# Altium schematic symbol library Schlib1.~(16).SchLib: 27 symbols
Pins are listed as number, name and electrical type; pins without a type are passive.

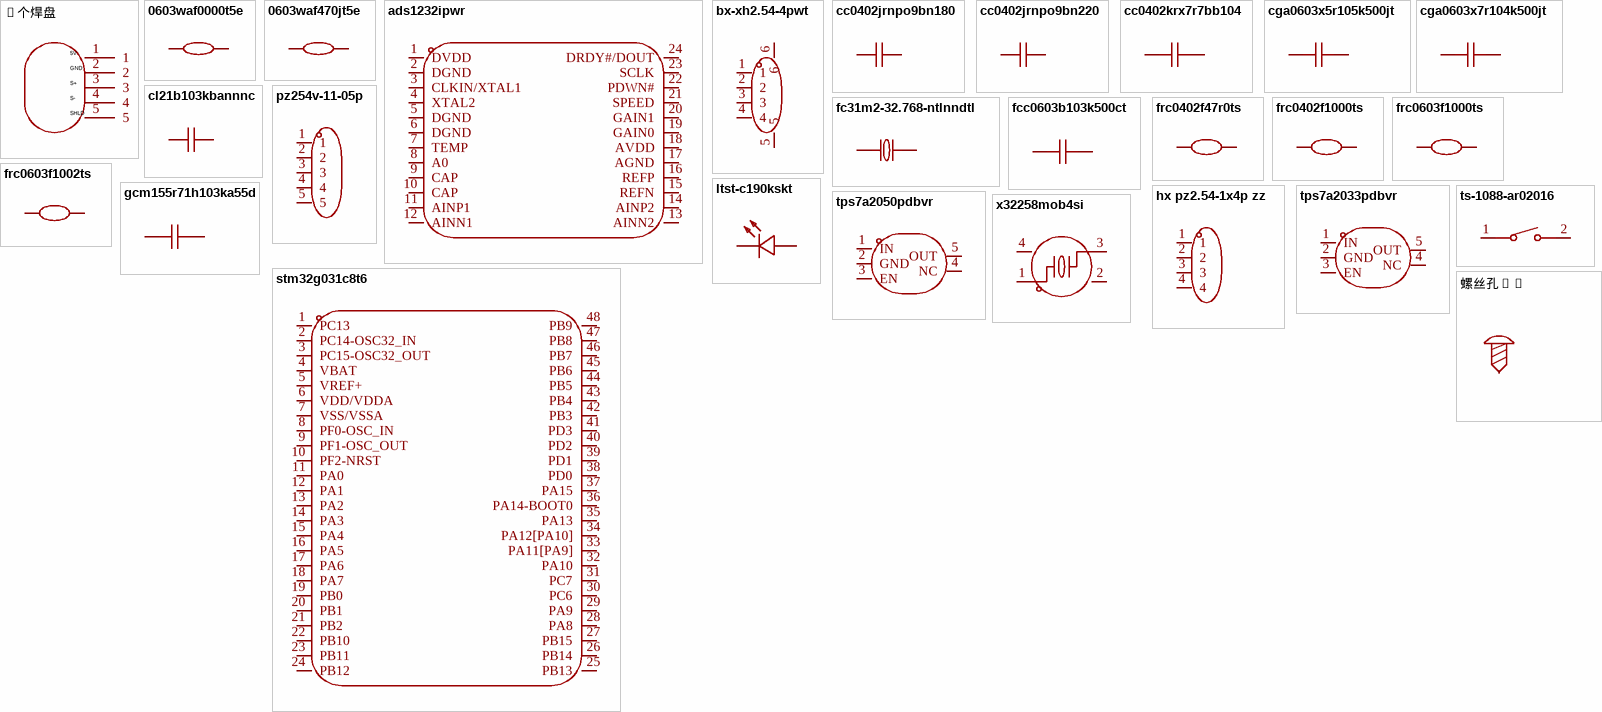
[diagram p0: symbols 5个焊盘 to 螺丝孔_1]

## 5个焊盘
designator U??  (value not drawn)
Convert to PCB: yes
pins: 1, 2, 3, 4, 5

## 0603waf0000t5e
designator R??  (value not drawn)
电阻类型:厚膜电阻;阻值:0Ω;精度:±1%;功率:100mW;工作电压:75V;温度系数:-;; Manufacturer: UNI-ROYAL(厚声); AddInBom: yes; ModelId: fc143cca1e79419f9cd78b61e9279f08; ModelName: R0603; ModelTransform: 31.8897,63.7794,0,90,0,0,0,0,0; Value: 0Ω; Tolerance: ±1%; Power(Watts): 100mW; Voltage-Supply(Max): 75V
footprint R0603
pins: 1, 2

## 0603waf470jt5e
designator R??  (value not drawn)
电阻类型:厚膜电阻;阻值:47Ω;精度:±1%;功率:100mW;工作电压:75V;温度系数:±100ppm/℃;; Manufacturer: UNI-ROYAL(厚声); AddInBom: yes; ModelId: fc143cca1e79419f9cd78b61e9279f08; ModelName: R0603; ModelTransform: 31.8897,63.7794,0,90,0,0,0,0,0; Value: 47Ω; Tolerance: ±1%; Power(Watts): 100mW; Voltage-Supply(Max): 75V
footprint R0603
pins: 1, 2

## ads1232ipwr
designator U??  (value not drawn)
分辨率(位):24;采样率:10Hz;工作电压:2.7V~5.3V;接口类型:SPI;; Manufacturer: TI(德州仪器); AddInBom: yes; ModelId: 57e278220af748a2882c4abba4094eb9; ModelName: TSSOP-24_L7.8-W4.4-H1.0-LS6.4-P0.65; ModelTransform: 252.188,307.086,0,90,0,0,0,0,0; Resolution (Bits): 24; Sampling Rate: 10Hz; number of channels: 2; Interface: SPI; differential input: 是; Clock/Oscillator: 内置；外置; Clock Frequency: 4.9152MHz；200kHz~8MHz; Voltage Reference: 外置; Programmable Gain: 支持; Temperature Sensors: 内置; ADC architecture: Sigma-Delta; Data rate: 80Hz；10Hz; Quiescent Current (Iq): 1.3uA; Full-Scale Range(FSR): 39mV；1.25V；19.5mV；2.5V
footprint TSSOP-24_L7.8-W4.4-P0.65-LS6.4-BL
footprint Model Name (Footprint not found)
pins: 1 DVDD, 2 DGND, 3 CLKIN/XTAL1, 4 XTAL2, 5 DGND, 6 DGND, 7 TEMP, 8 A0, 9 CAP, 10 CAP, 11 AINP1, 12 AINN1, 13 AINN2, 14 AINP2, 15 REFN, 16 REFP, 17 AGND, 18 AVDD, 19 GAIN0, 20 GAIN1, 21 SPEED, 22 PDWN#, 23 SCLK, 24 DRDY#/DOUT

## bx-xh2.54-4pwt
designator U??  (value not drawn)
插针结构:1x4P;间距:2.5mm;安装方式:卧贴;参考系列:XH;总PIN数:4P;排数:1;每排PIN数:4;行距:-;额定电流:3A;触头材质:黄铜;触头镀层:锡;工作温度:-25℃~+85℃;; Manufacturer: Bossie(博锡); AddInBom: yes; ModelId: fc4292fdbd0c45d68488b12ac9a84ffb; ModelName: CONN-SMD_4P-P2.50_BX-XH2.54-4PWT; ModelTransform: 590.55,413.385,0,0,0,0,-0.003,-11.339,0; Pins Structure: 1x4P; Pitch: 2.5mm; Reference Series: XH; Number of PINs Per Row: 4; Current Rating: 3A; Voltage Rating: 250V; Supplementary Features: 辅助焊脚; Z-Height of the Board: 6.2mm; X-Length of Bottom Edge on Board (Spacing Line): 15mm; Y-Width of Bottom Edge on Board: 10.5mm
footprint CONN-SMD_4P-P2.50_BX-XH2.54-4PWT
pins: 1, 2, 3, 4, 5, 6

## cc0402jrnpo9bn180
designator C??  (value not drawn)
容值:18pF;精度:±5%;额定电压:50V;温度系数:NP0;; Manufacturer: YAGEO(国巨); AddInBom: yes; ModelId: 36a51122f27c49738f86b3bfa98863e0; ModelName: C0402_L1.0-W0.5-H0.5; ModelTransform: 39.37,19.685,0,0,0,0,0,0,0; Value: 18pF; Tolerance: ±5%; Voltage Rating: 50V; Temperature Coefficient: NP0
footprint C0402
pins: 1, 2

## cc0402jrnpo9bn220
designator C??  (value not drawn)
容值:22pF;精度:±5%;额定电压:50V;温度系数:NP0;; Manufacturer: YAGEO(国巨); AddInBom: yes; ModelId: 36a51122f27c49738f86b3bfa98863e0; ModelName: C0402_L1.0-W0.5-H0.5; ModelTransform: 39.37,19.685,0,0,0,0,0,0,0; Value: 22pF; Tolerance: ±5%; Voltage Rating: 50V; Temperature Coefficient: NP0
footprint C0402
pins: 1, 2

## cc0402krx7r7bb104
designator C??  (value not drawn)
容值:100nF;精度:±10%;额定电压:16V;温度系数:X7R;; Manufacturer: YAGEO(国巨); AddInBom: yes; ModelId: 36a51122f27c49738f86b3bfa98863e0; ModelName: C0402_L1.0-W0.5-H0.5; ModelTransform: 39.37,19.685,0,0,0,0,0,0,0; Value: 100nF; Tolerance: ±10%; Voltage Rating: 16V; Temperature Coefficient: X7R
footprint C0402
pins: 1, 2

## cga0603x5r105k500jt
designator C??  (value not drawn)
容值:1uF;精度:±10%;额定电压:50V;温度系数:X5R;; Manufacturer: HRE(芯声); AddInBom: yes; ModelId: ac125912035d415993ca9572d50418b1; ModelName: C0603_L1.6-W0.8-H0.8; ModelTransform: 62.992,31.496,0,0,0,0,0,0,0; Value: 1uF; Tolerance: ±10%; Voltage Rating: 50V; Temperature Coefficient: X5R
footprint C0603
pins: 1, 2

## cga0603x7r104k500jt
designator C??  (value not drawn)
容值:100nF;精度:±10%;额定电压:50V;温度系数:X7R;; Manufacturer: HRE(芯声); AddInBom: yes; ModelId: ac125912035d415993ca9572d50418b1; ModelName: C0603_L1.6-W0.8-H0.8; ModelTransform: 62.992,31.496,0,0,0,0,0,0,0; Value: 100nF; Tolerance: ±10%; Voltage Rating: 50V; Temperature Coefficient: X7R
footprint C0603
footprint Model Name (Footprint not found)
pins: 1, 2

## cl21b103kbannnc
designator C??  (value not drawn)
容值:10nF;精度:±10%;额定电压:50V;温度系数:X7R;; Manufacturer: SAMSUNG(三星); AddInBom: yes; ModelId: 1ba041120af144c991958decab20d241; ModelName: C0805_L2.0-W1.3-H1.3; ModelTransform: 78.74,51.181,0,0,0,0,0,0.0005,0; Value: 10nF; Tolerance: ±10%; Voltage Rating: 50V; Temperature Coefficient: X7R
footprint C0805
pins: 1, 2

## fc31m2-32.768-ntlnndtl
designator U??  (value not drawn)
晶振类型:贴片晶振;频率:32.768kHz;常温频差:±10ppm;负载电容:12.5pF;频率稳定度:±10ppm;; Manufacturer: HCI(杭晶); AddInBom: yes; ModelId: 762d7afc596f4558a373612390f4386d; ModelName: CRYSTAL-SMD_L3.2-W1.5-1; ModelTransform: 125.984,59.055,0,0,0,0,0,0,0; Normal temperature Frequency Tolerance: ±10ppm; Load Capacitance: 12.5pF; Equivalent Series Resistance(ESR): 70kΩ
footprint CRYSTAL-SMD_L3.2-W1.5
pins: 1, 2

## fcc0603b103k500ct
designator C??  (value not drawn)
容值:10nF;精度:±10%;额定电压:50V;温度系数:X7R;; Manufacturer: FOJAN(富捷); AddInBom: yes; ModelId: ac125912035d415993ca9572d50418b1; ModelName: C0603_L1.6-W0.8-H0.8; ModelTransform: 62.992,31.496,0,0,0,0,0,0,0; Value: 10nF; Tolerance: ±10%; Voltage Rating: 50V; Temperature Coefficient: X7R
footprint C0603
pins: 1, 2

## frc0402f47r0ts
designator R??  (value not drawn)
电阻类型:厚膜电阻;阻值:47Ω;精度:±1%;功率:62.5mW;工作电压:50V;温度系数:±100ppm/℃;; Manufacturer: FOJAN(富捷); AddInBom: yes; ModelId: 98c88bc2b9094f218f3a3e30a7012738; ModelName: R0402_L1.0-W0.5-H0.4; ModelTransform: 39.37,19.685,0,0,0,0,0,0,0; Value: 47Ω; Tolerance: ±1%; Power(Watts): 62.5mW; Voltage-Supply(Max): 50V
footprint R0402
pins: 1, 2

## frc0402f1000ts
designator R??  (value not drawn)
电阻类型:厚膜电阻;阻值:100Ω;精度:±1%;功率:62.5mW;工作电压:50V;温度系数:±100ppm/℃;; Manufacturer: FOJAN(富捷); AddInBom: yes; ModelId: 98c88bc2b9094f218f3a3e30a7012738; ModelName: R0402_L1.0-W0.5-H0.4; ModelTransform: 39.37,19.685,0,0,0,0,0,0,0; Value: 100Ω; Tolerance: ±1%; Power(Watts): 62.5mW; Voltage-Supply(Max): 50V
footprint R0402
pins: 1, 2

## frc0603f1000ts
designator R??  (value not drawn)
电阻类型:厚膜电阻;阻值:100Ω;精度:±1%;功率:100mW;工作电压:75V;温度系数:±100ppm/℃;; Manufacturer: FOJAN(富捷); AddInBom: yes; ModelId: fc143cca1e79419f9cd78b61e9279f08; ModelName: R0603; ModelTransform: 31.8897,63.7794,0,90,0,0,0,0,0; Value: 100Ω; Tolerance: ±1%; Power(Watts): 100mW; Voltage-Supply(Max): 75V
footprint R0603
pins: 1, 2

## frc0603f1002ts
designator R??  (value not drawn)
电阻类型:厚膜电阻;阻值:10kΩ;精度:±1%;功率:100mW;工作电压:75V;温度系数:±100ppm/℃;; Manufacturer: FOJAN(富捷); AddInBom: yes; ModelId: fc143cca1e79419f9cd78b61e9279f08; ModelName: R0603; ModelTransform: 31.8897,63.7794,0,90,0,0,0,0,0; Value: 10kΩ; Tolerance: ±1%; Power(Watts): 100mW; Voltage-Supply(Max): 75V
footprint R0603
pins: 1, 2

## gcm155r71h103ka55d
designator C??  (value not drawn)
容值:10nF;精度:±10%;额定电压:50V;温度系数:X7R;; Manufacturer: muRata(村田); AddInBom: yes; ModelId: 36a51122f27c49738f86b3bfa98863e0; ModelName: C0402_L1.0-W0.5-H0.5; ModelTransform: 39.37,19.685,0,0,0,0,0,0,0; Value: 10nF; Tolerance: ±10%; Voltage Rating: 50V; Temperature Coefficient: X7R
footprint C0402
pins: 1, 2

## hx pz2.54-1x4p zz
designator U??  (value not drawn)
插针结构:1x4P;间距:2.54mm;行距:-;圆针/方针:方针;安装方式:直插;排数:单排;总PIN位数:4P;额定电流:3A;额定电压:1kV;配合针长度:6mm;塑高:2.5mm;端接针长度:3mm;触头材质:黄铜;触头镀层:金;工作温度:-40℃~+105℃;颜色:黑色;; Manufacturer: hanxia(韩下); AddInBom: yes; ModelId: 112f4d05e8d64e99ab9a333894bea4f9; ModelName: HDR-TH_4P-P2.54-M-LI-1X4P; ModelTransform: 399.999,104.7242,0,0,0,0,0,0,-118.11; Pin Structure: 1x4P; Pitch: 2.54mm; Circluar Pins/Square Pins: 方针; Current Rating: 3A; Voltage Rating (Max): 1kV
footprint HDR-TH_4P-P2.54-V-M
pins: 1, 2, 3, 4

## ltst-c190kskt
designator LED??  (value not drawn)
灯头类型:-;发光颜色:黄色;正向压降(Vf):2.1V;功率:75mW;正向电流:20mA;波长:584.5nm~597nm;二极管配置:独立二极管;透镜颜色:无色透明透镜;色温:-;发光强度:104mcd;发光角度:130°;载带方式:-;工作温度:-30℃~+85℃;; Manufacturer: LITEON(光宝); AddInBom: yes; ModelId: 1f0d29a91be547639d425604e9b96ebb; ModelName: LED0603-RD; ModelTransform: 63.7794,32.283,0,0,0,0,0,0,0; Illumination Color: 黄色; Voltage - Forward(Vf): 2.1V; Power(Watts): 75mW; Forward Current: 20mA; Peak Wavelength: 588nm; Diode Configuration: 独立二极管; Lens Color: 无色透明透镜; Luminous Intensity: 104mcd; Viewing Angle: 130°
footprint LED0603-RD
pins: 1 -, 2 +

## pz254v-11-05p
designator H??  (value not drawn)
插针结构:1x5P;间距:2.54mm;行距:-;圆针/方针:方针;安装方式:直插;排数:单排;总PIN位数:5P;额定电流:3A;额定电压:250V;配合针长度:6mm;塑高:2.5mm;端接针长度:3mm;触头材质:黄铜;触头镀层:-;工作温度:-40℃~+105℃;颜色:黑色;; Manufacturer: XFCN(兴飞); AddInBom: yes; ModelId: 47d466e4a34f4fc5bc626cf773a24dd5; ModelName: HDR-TH_5P-P2.54-M-LI-1X5P; ModelTransform: 499.999,100,0,0,0,0,0,0,-118.11; Pin Structure: 1x5P; Pitch: 2.54mm; Circluar Pins/Square Pins: 方针; Current Rating: 3A; Voltage Rating (Max): 250V
footprint HDR-TH_5P-P2.54-V-M
pins: 1, 2, 3, 4, 5

## stm32g031c8t6
designator U??  (value not drawn)
CPU内核:ARM Cortex-M0+;CPU最大主频:64MHz;CPU位数:32 Bit;; Manufacturer: ST(意法半导体); AddInBom: yes; ModelId: 093be70396ff421eb2cdb946d5311efc; ModelName: LQFP-48_L7.0-W7.0-H1.4-LS9.0-P0.50; ModelTransform: 354.331,354.331,0,0,0,0,0,0,0; CPU Maximum Speed: 64MHz; Core Size: 32 Bit; Program Storage Size: 64KB; Program Memory Type: FLASH; RAM Size: 8KB; Number of I/O: 44; ADC (Bit): 12bit; Oscillator Type: 内置+外置; Voltage - Supply: 1.7V~3.6V
footprint LQFP-48_L7.0-W7.0-P0.50-LS9.0-BL
pins: 1 PC13, 2 PC14-OSC32_IN, 3 PC15-OSC32_OUT, 4 VBAT, 5 VREF+, 6 VDD/VDDA, 7 VSS/VSSA, 8 PF0-OSC_IN, 9 PF1-OSC_OUT, 10 PF2-NRST, 11 PA0, 12 PA1, 13 PA2, 14 PA3, 15 PA4, 16 PA5, 17 PA6, 18 PA7, 19 PB0, 20 PB1, 21 PB2, 22 PB10, 23 PB11, 24 PB12, 25 PB13, 26 PB14, 27 PB15, 28 PA8, 29 PA9, 30 PC6, 31 PC7, 32 PA10, 33 PA11[PA9], 34 PA12[PA10], 35 PA13, 36 PA14-BOOT0, 37 PA15, 38 PD0, 39 PD1, 40 PD2, 41 PD3, 42 PB3, 43 PB4, 44 PB5, 45 PB6, 46 PB7, 47 PB8, 48 PB9

## tps7a2033pdbvr
designator U??  (value not drawn)
输出类型:固定;最大输入电压:6V;输出电压:3.3V;输出电流:300mA;输出极性:正极;; Manufacturer: TI(德州仪器); AddInBom: yes; ModelId: 7ba65df16e7b4570af156e925f9c37fe; ModelName: SOT-23-5_L2.9-W1.6-P0.95-LS2.8-BR; ModelTransform: 114.173,114.173,0,90,0,0,0,0,0; Output Type: 固定; Maximum Input Voltage: 6V; Output Voltage: 3.3V; Output Current: 300mA; Dropout Voltage: 140mV@(300mA); standby current: 15uA; Output Polarity: 正极; Number of Outputs: 1
footprint SOT-23-5_L2.9-W1.6-P0.95-LS2.8-BR
pins: 1 IN, 2 GND, 3 EN, 4 NC, 5 OUT

## tps7a2050pdbvr
designator U??  (value not drawn)
输出极性:正极;工作电压:6V;输出电压:5V;输出电流:300mA;电源纹波抑制比(PSRR):65dB@(100Hz);输出类型:固定;; Manufacturer: TI(德州仪器); AddInBom: yes; ModelId: 7ba65df16e7b4570af156e925f9c37fe; ModelName: SOT-23-5_L2.9-W1.6-P0.95-LS2.8-BR; ModelTransform: 114.173,114.173,0,90,0,0,0,0,0; Output Configuration: 正极; Voltage - Supply: 6V; Output Voltage: 5V; Output Current: 300mA; Voltage Dropout: 140mV@(300mA); standby current: 6.5uA; Noise: 10uVrms; Output Type: 固定; Number of Outputs: 1
footprint SOT-23-5_L2.9-W1.6-P0.95-LS2.8-BR
pins: 1 IN, 2 GND, 3 EN, 4 NC, 5 OUT

## ts-1088-ar02016
designator SW??  (value not drawn)
电路结构:单刀单掷;按钮形状:圆形按钮;作用力:1.6N;安装方式:立贴;开关长度:3.9mm;开关宽度:3mm;开关高度:2mm;带支架:不带支架;触点电流:50mA;额定电压:12V;带灯:-;工作寿命:10万次;; Manufacturer: XUNPU(讯普); AddInBom: yes; ModelId: b26698b69f274ffabef8a26c7d0e5dd1; ModelName: SW-SMD_L3.9-W2.9-H2.0-LS4.8; ModelTransform: 188.976,114.174,0,0,0,0,0,0,0; Circuit: 单刀单掷; Actuator Style: 圆形按钮; Operating Force: 1.6N; Switch Height: 2mm; with Bracket: 不带支架; Contact Current: 50mA; Voltage Rating: 12V; Actuator/Cap Color: 黑色; Life: 10万次
footprint SW-SMD_L3.9-W3.0-P4.45
pins: 1, 2

## x32258mob4si
designator X??  (value not drawn)
晶振类型:贴片晶振;频率:8MHz;常温频差:±10ppm;负载电容:12pF;频率稳定度:±20ppm;; Manufacturer: YXC(扬兴晶振); AddInBom: yes; ModelId: ff2dfd5650294453a14147960efe1838; ModelName: CRYSTAL-SMD_4P-L3.2-W2.5-BL; ModelTransform: 125.984,98.425,0,0,0,0,0,0,0; Value: 8MHz; Normal temperature Frequency Tolerance: ±10ppm; Load Capacitance: 12pF; Frequency Stability: ±20ppm; Equivalent Series Resistance(ESR): 180Ω
footprint CRYSTAL-SMD_4P-L3.2-W2.5-BL
pins: 1, 2 GND, 3, 4 GND

## 螺丝孔_1
designator *?  (value not drawn)
pins: 1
